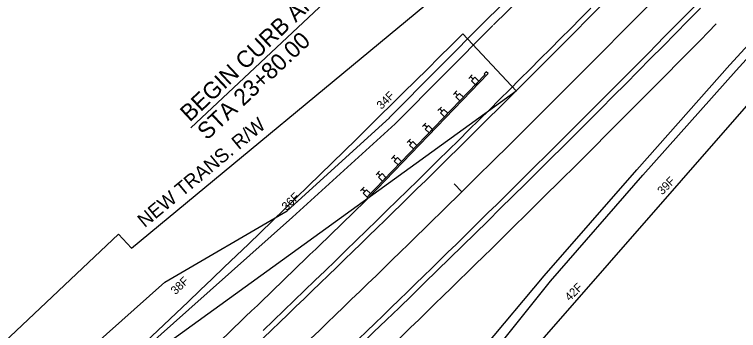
# Model space of a CAD drawing. Extents: x 1623239 to 1625698, y 1118659 to 1120751.
# Drawn here: x 1624416.9 to 1624676.8, y 1119749.3 to 1119862.6 of the extents above; entities that cross this region are included whole.
import ezdxf

# ---------------------------------------------------------------- set-up
doc = ezdxf.new("R2010")
doc.units = 0
for name, color, linetype in [('RD_HC_CL_Rel', 7, 'Continuous'), ('RD_HC_Data_Tic', 7, 'Continuous'), ('RD_PD_CstnLmt', 7, 'Continuous'), ('RD_PD_CstnLmt_TX', 7, 'Continuous'), ('RD_PD_DR_ErosCtrl', 7, 'Continuous'), ('RD_PD_Final_TrvlWay', 7, 'Continuous'), ('RD_PD_Final_TX', 7, 'Continuous'), ('RD_PD_GR', 7, 'Continuous'), ('RD_PD_PaveShd', 7, 'Continuous'), ('RD_PD_RW', 7, 'Continuous'), ('RD_Sketch8', 7, 'Continuous')]:
    doc.layers.add(name, color=color, linetype=linetype)

msp = doc.modelspace()

# ---------------------------------------------------------------- linework, layer by layer
at = {"layer": 'RD_HC_CL_Rel'}
msp.add_arc((1620034.69, 1124419.96), 6480, 313.16267, 315.457254, dxfattribs=at)
at = {"layer": 'RD_HC_Data_Tic'}
msp.add_line((1624577.5, 1119799), (1624574.7, 1119801.85), dxfattribs=at)
at = {"layer": 'RD_PD_CstnLmt'}
for p, q in [((1624588.92, 1119858.88), (1624612.6, 1119882.23)), ((1624673.75, 1119844.52), (1624707.3, 1119881.4)), ((1624553.56, 1119823.35), (1624588.65, 1119858.61)), ((1624640.29, 1119806.89), (1624673.75, 1119844.52)), ((1624516.75, 1119789.87), (1624553.56, 1119823.35)), ((1624607.1, 1119768.89), (1624640.29, 1119806.89)), ((1624479.55, 1119756.84), (1624516.75, 1119789.87)), ((1624574.57, 1119730.15), (1624607.1, 1119768.89)), ((1624463.59, 1119742.69), (1624479.55, 1119756.84))]:
    msp.add_line(p, q, dxfattribs=at)
at = {"layer": 'RD_PD_DR_ErosCtrl'}
for p, q in [((1624586.54, 1119860.74), (1624612.56, 1119886.58)), ((1624675.98, 1119842.52), (1624709.49, 1119879.36)), ((1624551.44, 1119825.47), (1624586.54, 1119860.74)), ((1624642.54, 1119804.9), (1624675.98, 1119842.52)), ((1624514.76, 1119792.12), (1624551.54, 1119825.57)), ((1624609.39, 1119766.95), (1624642.54, 1119804.9)), ((1624470.93, 1119766.57), (1624514.76, 1119792.12)), ((1624433.57, 1119733.46), (1624470.93, 1119766.57)), ((1624577.5, 1119727.43), (1624609.39, 1119766.95))]:
    msp.add_line(p, q, dxfattribs=at)
at = {"layer": 'RD_PD_Final_TrvlWay'}
for radius in [6468, 6492]:
    msp.add_arc((1620034.69, 1124419.96), radius, 313.16267, 315.457254, dxfattribs=at)
at = {"layer": 'RD_PD_Final_TX'}
msp.add_line((1624480.25, 1119821.93), (1624568.08, 1119904.3), dxfattribs=at)
at = {"layer": 'RD_PD_GR'}
for p, q in [((1624543.88, 1119796.74), (1624586.92, 1119841.37)), ((1624586.2, 1119842.06), (1624585.5, 1119841.34)), ((1624585.5, 1119841.34), (1624585.86, 1119841)), ((1624586.92, 1119841.37), (1624586.2, 1119842.06)), ((1624585.86, 1119841), (1624543.52, 1119797.09)), ((1624581.27, 1119840.91), (1624580.05, 1119839.65)), ((1624581.56, 1119839.42), (1624580.66, 1119840.28)), ((1624580.95, 1119838.79), (1624582.17, 1119840.05)), ((1624582.39, 1119837.4), (1624580.95, 1119838.79)), ((1624582.17, 1119840.05), (1624583.61, 1119838.66)), ((1624583.61, 1119838.66), (1624582.39, 1119837.4)), ((1624575.71, 1119835.16), (1624574.5, 1119833.9)), ((1624576.01, 1119833.66), (1624575.11, 1119834.53)), ((1624575.4, 1119833.03), (1624576.61, 1119834.29)), ((1624576.61, 1119834.29), (1624578.05, 1119832.9)), ((1624576.84, 1119831.64), (1624575.4, 1119833.03)), ((1624578.05, 1119832.9), (1624576.84, 1119831.64)), ((1624570.16, 1119829.4), (1624568.95, 1119828.14)), ((1624570.45, 1119827.9), (1624569.55, 1119828.77)), ((1624569.84, 1119827.27), (1624571.06, 1119828.53)), ((1624571.06, 1119828.53), (1624572.5, 1119827.14)), ((1624571.28, 1119825.88), (1624569.84, 1119827.27)), ((1624572.5, 1119827.14), (1624571.28, 1119825.88)), ((1624564.61, 1119823.64), (1624563.39, 1119822.38)), ((1624564.9, 1119822.14), (1624564, 1119823.01)), ((1624564.29, 1119821.51), (1624565.51, 1119822.77)), ((1624565.73, 1119820.12), (1624564.29, 1119821.51)), ((1624565.51, 1119822.77), (1624566.95, 1119821.38)), ((1624566.95, 1119821.38), (1624565.73, 1119820.12)), ((1624559.05, 1119817.88), (1624557.84, 1119816.62)), ((1624559.35, 1119816.38), (1624558.45, 1119817.25)), ((1624558.74, 1119815.75), (1624559.95, 1119817.01)), ((1624560.18, 1119814.37), (1624558.74, 1119815.75)), ((1624559.95, 1119817.01), (1624561.39, 1119815.62)), ((1624561.39, 1119815.62), (1624560.18, 1119814.37)), ((1624553.5, 1119812.12), (1624552.28, 1119810.86)), ((1624553.79, 1119810.62), (1624552.89, 1119811.49)), ((1624553.18, 1119810), (1624554.4, 1119811.25)), ((1624554.62, 1119808.61), (1624553.18, 1119810)), ((1624554.4, 1119811.25), (1624555.84, 1119809.87)), ((1624555.84, 1119809.87), (1624554.62, 1119808.61)), ((1624547.95, 1119806.36), (1624546.73, 1119805.1)), ((1624548.24, 1119804.87), (1624547.34, 1119805.73)), ((1624547.63, 1119804.24), (1624548.85, 1119805.5)), ((1624548.85, 1119805.5), (1624550.28, 1119804.11)), ((1624549.07, 1119802.85), (1624547.63, 1119804.24)), ((1624550.28, 1119804.11), (1624549.07, 1119802.85)), ((1624542.39, 1119800.61), (1624541.18, 1119799.35)), ((1624542.68, 1119799.11), (1624541.78, 1119799.98)), ((1624542.08, 1119798.48), (1624543.29, 1119799.74)), ((1624543.29, 1119799.74), (1624544.73, 1119798.35)), ((1624543.52, 1119797.09), (1624542.08, 1119798.48)), ((1624544.73, 1119798.35), (1624543.52, 1119797.09)), ((1624543.52, 1119797.09), (1624543.88, 1119796.74))]:
    msp.add_line(p, q, dxfattribs=at)
msp.add_arc((1620034.75, 1124419.9), 6458, 313.457809, 314.284639, dxfattribs=at)
at = {"layer": 'RD_PD_PaveShd'}
for radius, start, end in [(6466, 313.75143, 315.213737), (6494, 313.664525, 315.457254)]:
    msp.add_arc((1620034.69, 1124419.96), radius, start, end, dxfattribs=at)
at = {"layer": 'RD_PD_RW'}
for p, q in [((1624458.96, 1119778.79), (1624670.67, 1119953.92)), ((1624550.56, 1119682.16), (1624683.49, 1119834.14)), ((1624236, 1119579.09), (1624454.27, 1119783.79)), ((1624458.96, 1119778.79), (1624454.27, 1119783.79))]:
    msp.add_line(p, q, dxfattribs=at)
at = {"layer": 'RD_Sketch8'}
for p, q in [((1624597.05, 1119835.21), (1624577.89, 1119855.65)), ((1624437.6, 1119720.17), (1624597.05, 1119835.21))]:
    msp.add_line(p, q, dxfattribs=at)
for radius, end in [(6502, 315.457254), (6440, 314.867171)]:
    msp.add_arc((1620034.69, 1124419.96), radius, 313.16267, end, dxfattribs=at)

# ---------------------------------------------------------------- texts
at = {"layer": 'RD_PD_CstnLmt_TX'}
for s, rotation, p in [('34F', 44.5114, (1624548.66, 1119828.35)), ('39F', 44.9535, (1624649.47, 1119797.69)), ('36F', 44.0693, (1624514.56, 1119792.06)), ('38F', 43.6272, (1624474.72, 1119761.91)), ('42F', 44.5114, (1624616.22, 1119759.62))]:
    msp.add_text(s, height=3, rotation=rotation, dxfattribs=at).set_placement(p)
at = {"layer": 'RD_PD_Final_TX'}
for s, p in [('BEGIN CURB AND GUTTER', (1624479.85, 1119823.82)), ('STA 23+80.00', (1624486.01, 1119817.25))]:
    msp.add_text(s, height=6, rotation=43.1625, dxfattribs=at).set_placement(p)
at = {"layer": 'RD_PD_RW'}
msp.add_text('NEW TRANS. R/W', height=5, rotation=39.5981, dxfattribs=at).set_placement((1624463.67, 1119785.93))

doc.saveas('drawing.dxf')
